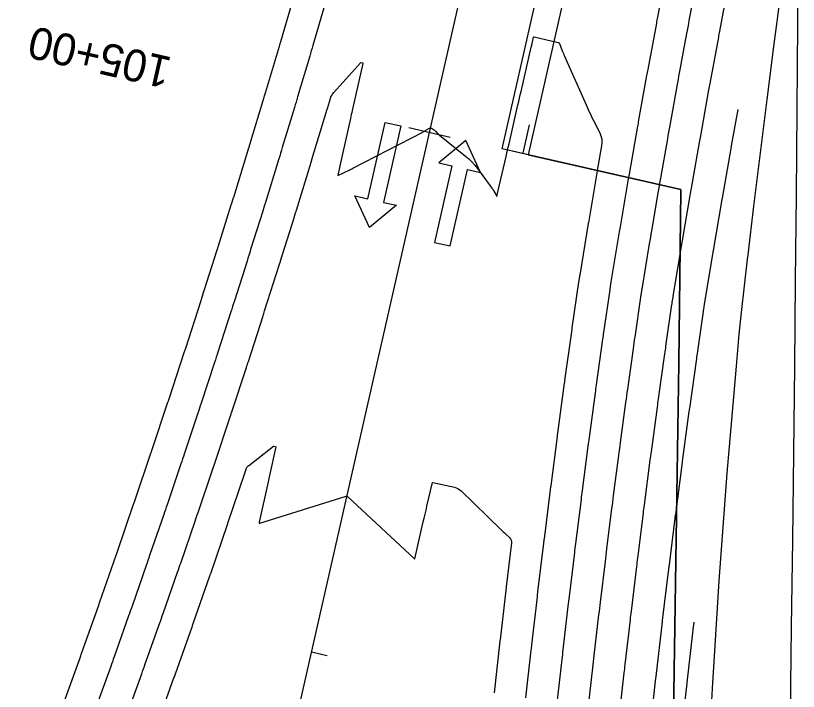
# Model space of a CAD drawing. Extents: x 1710723 to 1713003, y 548603 to 551142.
# Drawn here: x 1712345.3 to 1712492.2, y 550298.2 to 550424.9 of the extents above; entities that cross this region are included whole.
import ezdxf

# ---------------------------------------------------------------- set-up
doc = ezdxf.new("R2010")
doc.units = 0
for name, color, linetype in [('R_Contours', 7, 'Continuous'), ('R_Horz Alg', 7, 'Continuous'), ('R_Horz Alg Annot', 7, 'Continuous'), ('R_MOT', 7, 'Continuous'), ('R_No Plot', 7, 'Continuous'), ('R_Striping', 7, 'Continuous')]:
    doc.layers.add(name, color=color, linetype=linetype)

msp = doc.modelspace()

# ---------------------------------------------------------------- linework, layer by layer
at = {"layer": 'R_Contours'}
for points in [[(1712467.36, 550433.38), (1712465.71, 550424.66), (1712465.65, 550424.38), (1712465.6, 550424.1), (1712465.55, 550423.81), (1712465.5, 550423.53), (1712463.89, 550414.84), (1712463.83, 550414.55), (1712463.78, 550414.26), (1712463.73, 550413.96), (1712463.67, 550413.67), (1712462.11, 550405.01), (1712462.06, 550404.71), (1712462, 550404.4), (1712461.95, 550404.1), (1712461.89, 550403.8), (1712460.38, 550395.17), (1712460.32, 550394.86), (1712460.27, 550394.54), (1712460.22, 550394.23), (1712460.16, 550393.92), (1712458.69, 550385.32), (1712458.64, 550385), (1712458.58, 550384.67), (1712458.53, 550384.35), (1712458.48, 550384.02), (1712456.98, 550375.01), (1712456.96, 550374.9), (1712456.94, 550374.79), (1712456.92, 550374.68), (1712456.91, 550374.57), (1712456.76, 550373.68), (1712456.76, 550373.64), (1712456.75, 550373.6), (1712456.74, 550373.56), (1712456.74, 550373.52), (1712455.58, 550365.49), (1712455.54, 550365.18), (1712455.49, 550364.86), (1712455.45, 550364.55), (1712455.4, 550364.24), (1712454.21, 550355.67), (1712454.16, 550355.3), (1712454.11, 550354.92), (1712454.06, 550354.55), (1712454, 550354.18), (1712452.87, 550345.76), (1712452.82, 550345.37), (1712452.77, 550344.97), (1712452.71, 550344.58), (1712452.66, 550344.19), (1712451.58, 550335.83), (1712451.52, 550335.42), (1712451.47, 550335.01), (1712451.42, 550334.6), (1712451.37, 550334.19), (1712450.33, 550325.9), (1712450.27, 550325.47), (1712450.22, 550325.04), (1712450.17, 550324.62), (1712450.12, 550324.19), (1712449.12, 550315.95), (1712449.07, 550315.51), (1712449.02, 550315.06), (1712448.96, 550314.62), (1712448.91, 550314.17), (1712447.96, 550305.99), (1712447.91, 550305.53), (1712447.86, 550305.07), (1712447.81, 550304.61), (1712447.75, 550304.15), (1712446.85, 550296.02)], [(1712452.72, 550294.9), (1712453.58, 550302.57), (1712453.64, 550303.15), (1712453.71, 550303.74), (1712453.78, 550304.33), (1712453.85, 550304.92), (1712454.73, 550312.55), (1712454.8, 550313.14), (1712454.87, 550313.73), (1712454.94, 550314.33), (1712455.01, 550314.92), (1712455.93, 550322.52), (1712456, 550323.12), (1712456.07, 550323.71), (1712456.15, 550324.31), (1712456.22, 550324.91), (1712457.17, 550332.48), (1712457.25, 550333.08), (1712457.32, 550333.69), (1712457.4, 550334.29), (1712457.48, 550334.89), (1712458.46, 550342.43), (1712458.54, 550343.04), (1712458.62, 550343.65), (1712458.7, 550344.25), (1712458.78, 550344.86), (1712459.79, 550352.36), (1712459.87, 550352.98), (1712459.96, 550353.6), (1712460.04, 550354.21), (1712460.13, 550354.83), (1712461.19, 550362.45), (1712461.27, 550362.99), (1712461.34, 550363.54), (1712461.42, 550364.08), (1712461.5, 550364.62), (1712462.58, 550372.13), (1712462.59, 550372.2), (1712462.6, 550372.27), (1712462.61, 550372.35), (1712462.62, 550372.42), (1712462.77, 550373.31), (1712462.78, 550373.38), (1712462.79, 550373.46), (1712462.81, 550373.54), (1712462.82, 550373.61), (1712464.23, 550382.12), (1712464.33, 550382.73), (1712464.44, 550383.34), (1712464.54, 550383.95), (1712464.64, 550384.56), (1712465.91, 550391.99), (1712466.02, 550392.6), (1712466.12, 550393.21), (1712466.23, 550393.83), (1712466.34, 550394.44), (1712467.64, 550401.84), (1712467.74, 550402.46), (1712467.85, 550403.08), (1712467.96, 550403.69), (1712468.07, 550404.31), (1712469.41, 550411.7), (1712469.52, 550412.31), (1712469.63, 550412.93), (1712469.74, 550413.54), (1712469.86, 550414.16), (1712471.23, 550421.54), (1712471.34, 550422.16), (1712471.45, 550422.77), (1712471.57, 550423.38), (1712471.68, 550423.99), (1712473.09, 550431.38)], [(1712458.54, 550293.21), (1712459.47, 550301.62), (1712459.52, 550302.01), (1712459.56, 550302.41), (1712459.61, 550302.81), (1712459.65, 550303.21), (1712460.63, 550311.61), (1712460.67, 550312.01), (1712460.72, 550312.4), (1712460.77, 550312.8), (1712460.81, 550313.2), (1712461.83, 550321.6), (1712461.88, 550321.99), (1712461.92, 550322.39), (1712461.97, 550322.78), (1712462.02, 550323.17), (1712463.08, 550331.58), (1712463.12, 550331.97), (1712463.17, 550332.36), (1712463.22, 550332.74), (1712463.27, 550333.13), (1712464.37, 550341.55), (1712464.42, 550341.93), (1712464.47, 550342.32), (1712464.52, 550342.7), (1712464.57, 550343.08), (1712465.71, 550351.51), (1712465.76, 550351.89), (1712465.81, 550352.27), (1712465.86, 550352.65), (1712465.91, 550353.03), (1712467.09, 550361.46), (1712467.14, 550361.83), (1712467.2, 550362.21), (1712467.25, 550362.58), (1712467.3, 550362.95), (1712468.42, 550370.74), (1712468.44, 550370.84), (1712468.45, 550370.95), (1712468.47, 550371.05), (1712468.49, 550371.15), (1712468.63, 550372.04), (1712468.64, 550372.09), (1712468.65, 550372.13), (1712468.65, 550372.18), (1712468.66, 550372.22), (1712470.17, 550381.31), (1712470.23, 550381.66), (1712470.29, 550382.01), (1712470.35, 550382.37), (1712470.41, 550382.72), (1712471.86, 550391.21), (1712471.92, 550391.55), (1712471.97, 550391.89), (1712472.03, 550392.22), (1712472.09, 550392.56), (1712473.59, 550401.1), (1712473.65, 550401.43), (1712473.71, 550401.75), (1712473.76, 550402.07), (1712473.82, 550402.39), (1712475.37, 550410.99), (1712475.43, 550411.3), (1712475.48, 550411.6), (1712475.54, 550411.9), (1712475.59, 550412.2), (1712477.2, 550420.87), (1712477.25, 550421.15), (1712477.3, 550421.44), (1712477.36, 550421.72), (1712477.41, 550422.01), (1712479.07, 550430.74)], [(1712354.31, 550296.02), (1712357.41, 550304.65), (1712357.48, 550304.86), (1712357.56, 550305.07), (1712357.63, 550305.27), (1712357.7, 550305.48), (1712360.78, 550314.18), (1712360.85, 550314.37), (1712360.92, 550314.56), (1712360.99, 550314.75), (1712361.05, 550314.94), (1712364.11, 550323.71), (1712364.17, 550323.89), (1712364.23, 550324.06), (1712364.29, 550324.23), (1712364.35, 550324.41), (1712367.4, 550333.26), (1712367.45, 550333.42), (1712367.5, 550333.57), (1712367.56, 550333.73), (1712367.61, 550333.88), (1712370.64, 550342.83), (1712370.69, 550342.96), (1712370.73, 550343.09), (1712370.77, 550343.22), (1712370.82, 550343.35), (1712373.84, 550352.42), (1712373.87, 550352.52), (1712373.91, 550352.63), (1712373.94, 550352.73), (1712373.98, 550352.84), (1712376.97, 550361.95), (1712377.01, 550362.06), (1712377.04, 550362.17), (1712377.08, 550362.28), (1712377.11, 550362.39), (1712380.05, 550371.49), (1712380.09, 550371.6), (1712380.13, 550371.72), (1712380.17, 550371.84), (1712380.21, 550371.96), (1712383.09, 550381.02), (1712383.13, 550381.15), (1712383.17, 550381.29), (1712383.21, 550381.42), (1712383.26, 550381.55), (1712385.73, 550389.46), (1712385.77, 550389.59), (1712385.81, 550389.71), (1712385.85, 550389.84), (1712385.89, 550389.96), (1712386.16, 550390.82), (1712386.18, 550390.88), (1712386.18, 550390.9), (1712389.02, 550400.11), (1712389.07, 550400.28), (1712389.12, 550400.44), (1712389.17, 550400.61), (1712389.22, 550400.78), (1712391.91, 550409.66), (1712391.97, 550409.85), (1712392.03, 550410.04), (1712392.08, 550410.23), (1712392.14, 550410.42), (1712394.76, 550419.22), (1712394.83, 550419.43), (1712394.89, 550419.64), (1712394.95, 550419.86), (1712395.02, 550420.07), (1712397.59, 550428.88)], [(1712403.28, 550426.98), (1712401.03, 550419.29), (1712400.88, 550418.8), (1712400.74, 550418.32), (1712400.6, 550417.83), (1712400.45, 550417.35), (1712398.18, 550409.71), (1712398.03, 550409.21), (1712397.88, 550408.71), (1712397.73, 550408.21), (1712397.58, 550407.71), (1712395.3, 550400.2), (1712395.14, 550399.66), (1712394.97, 550399.12), (1712394.81, 550398.58), (1712394.64, 550398.04), (1712392.07, 550389.68), (1712392.04, 550389.6), (1712392.02, 550389.53), (1712392, 550389.46), (1712391.98, 550389.39), (1712391.71, 550388.52), (1712391.69, 550388.45), (1712391.66, 550388.38), (1712391.64, 550388.31), (1712391.62, 550388.24), (1712389.36, 550381.04), (1712389.19, 550380.5), (1712389.02, 550379.96), (1712388.85, 550379.42), (1712388.68, 550378.88), (1712386.31, 550371.43), (1712386.15, 550370.91), (1712385.98, 550370.39), (1712385.81, 550369.88), (1712385.65, 550369.36), (1712383.21, 550361.82), (1712383.05, 550361.33), (1712382.89, 550360.84), (1712382.73, 550360.35), (1712382.57, 550359.86), (1712380.07, 550352.23), (1712379.91, 550351.76), (1712379.76, 550351.3), (1712379.61, 550350.83), (1712379.45, 550350.37), (1712376.89, 550342.69), (1712376.74, 550342.23), (1712376.58, 550341.77), (1712376.42, 550341.3), (1712376.27, 550340.84), (1712373.67, 550333.17), (1712373.51, 550332.7), (1712373.36, 550332.24), (1712373.2, 550331.78), (1712373.04, 550331.32), (1712370.4, 550323.65), (1712370.24, 550323.19), (1712370.09, 550322.73), (1712369.93, 550322.27), (1712369.77, 550321.81), (1712367.09, 550314.14), (1712366.93, 550313.68), (1712366.77, 550313.23), (1712366.61, 550312.77), (1712366.45, 550312.32), (1712363.73, 550304.64), (1712363.57, 550304.19), (1712363.41, 550303.74), (1712363.25, 550303.28), (1712363.09, 550302.83), (1712360.33, 550295.16)], [(1712366.2, 550293.9), (1712368.93, 550301.48), (1712369.09, 550301.94), (1712369.26, 550302.41), (1712369.43, 550302.87), (1712369.59, 550303.34), (1712372.31, 550311.01), (1712372.47, 550311.46), (1712372.62, 550311.9), (1712372.78, 550312.34), (1712372.93, 550312.79), (1712375.64, 550320.56), (1712375.79, 550320.98), (1712375.94, 550321.4), (1712376.08, 550321.82), (1712376.23, 550322.24), (1712378.94, 550330.12), (1712379.07, 550330.52), (1712379.21, 550330.91), (1712379.34, 550331.31), (1712379.48, 550331.71), (1712382.18, 550339.7), (1712382.31, 550340.07), (1712382.43, 550340.44), (1712382.56, 550340.8), (1712382.68, 550341.17), (1712385.4, 550349.32), (1712385.5, 550349.64), (1712385.61, 550349.97), (1712385.72, 550350.29), (1712385.83, 550350.62), (1712388.56, 550358.95), (1712388.65, 550359.23), (1712388.74, 550359.51), (1712388.84, 550359.79), (1712388.93, 550360.07), (1712391.69, 550368.61), (1712391.76, 550368.84), (1712391.83, 550369.07), (1712391.91, 550369.29), (1712391.98, 550369.52), (1712394.78, 550378.32), (1712394.83, 550378.47), (1712394.88, 550378.63), (1712394.93, 550378.79), (1712394.97, 550378.94), (1712397.51, 550387.02), (1712397.53, 550387.08), (1712397.8, 550387.95), (1712397.84, 550388.08), (1712397.87, 550388.2), (1712397.91, 550388.33), (1712397.95, 550388.45), (1712400.78, 550397.65), (1712400.8, 550397.72), (1712400.83, 550397.79), (1712400.85, 550397.86), (1712400.87, 550397.93), (1712403.72, 550407.35), (1712403.74, 550407.4), (1712403.78, 550407.53), (1712404.32, 550409.37), (1712404.43, 550409.67), (1712404.57, 550409.96), (1712404.74, 550410.22), (1712404.94, 550410.48), (1712410.01, 550416.16), (1712410.02, 550416.16), (1712410.32, 550416.1), (1712410.36, 550416.08), (1712410.39, 550416.05), (1712410.4, 550416.02), (1712410.4, 550415.97), (1712408.42, 550407.1), (1712408.33, 550406.73), (1712408.25, 550406.36), (1712408.17, 550405.98), (1712408.08, 550405.61), (1712406.11, 550396.74), (1712406.07, 550396.6), (1712406.04, 550396.45), (1712405.71, 550394.96), (1712405.71, 550394.94), (1712405.71, 550394.93), (1712405.73, 550394.93), (1712405.75, 550394.93), (1712407.86, 550395.95), (1712408.03, 550396.03), (1712408.2, 550396.11), (1712408.37, 550396.2), (1712408.53, 550396.28), (1712421.65, 550403.09), (1712421.8, 550403.17), (1712421.95, 550403.25), (1712422.09, 550403.33), (1712422.24, 550403.41), (1712422.93, 550403.8), (1712423.02, 550403.84), (1712423.12, 550403.85), (1712423.22, 550403.83), (1712423.32, 550403.79), (1712423.7, 550403.55), (1712423.8, 550403.49), (1712423.89, 550403.42), (1712423.97, 550403.34), (1712424.05, 550403.26), (1712424.44, 550402.84), (1712424.53, 550402.74), (1712424.63, 550402.65), (1712424.73, 550402.56), (1712424.83, 550402.47), (1712429.66, 550398.59), (1712430.28, 550398.06), (1712430.87, 550397.49), (1712431.41, 550396.88), (1712431.92, 550396.24), (1712434.65, 550392.56), (1712434.74, 550392.42), (1712434.83, 550392.29), (1712434.92, 550392.15), (1712435, 550392.01), (1712435.55, 550391.03), (1712435.56, 550391.02), (1712435.57, 550391.01), (1712435.58, 550391.02), (1712435.58, 550391.04), (1712437.31, 550398.52), (1712437.44, 550399.11), (1712437.58, 550399.7), (1712437.71, 550400.28), (1712437.85, 550400.87), (1712439.53, 550408.18), (1712439.67, 550408.81), (1712439.82, 550409.44), (1712439.96, 550410.07), (1712440.11, 550410.71), (1712442.02, 550419.02), (1712442.06, 550419.19), (1712442.1, 550419.36), (1712442.44, 550420.87), (1712442.46, 550420.91), (1712442.48, 550420.93), (1712442.51, 550420.94), (1712442.55, 550420.94), (1712447.06, 550419.91), (1712447.15, 550419.88), (1712447.23, 550419.83), (1712447.29, 550419.76), (1712447.33, 550419.68), (1712447.84, 550418.34), (1712447.94, 550418.08), (1712448.05, 550417.83), (1712448.15, 550417.58), (1712448.26, 550417.33), (1712452.58, 550407.61), (1712452.85, 550407.02), (1712453.13, 550406.43), (1712453.41, 550405.84), (1712453.7, 550405.26), (1712454.87, 550402.94), (1712455.11, 550402.35), (1712455.25, 550401.74), (1712455.29, 550401.13), (1712455.23, 550400.49), (1712454.42, 550395.9), (1712454.42, 550395.86), (1712454.41, 550395.84), (1712452.75, 550386.08), (1712452.74, 550386.04), (1712452.73, 550386), (1712452.73, 550385.96), (1712452.72, 550385.92), (1712451.11, 550376.25), (1712451.1, 550376.18), (1712451.09, 550376.12), (1712451.08, 550376.05), (1712451.07, 550375.99), (1712450.9, 550374.95), (1712450.9, 550374.92), (1712450.89, 550374.92), (1712449.66, 550366.36), (1712449.65, 550366.28), (1712449.64, 550366.19), (1712449.63, 550366.11), (1712449.62, 550366.02), (1712448.29, 550356.51), (1712448.27, 550356.38), (1712448.25, 550356.25), (1712448.24, 550356.13), (1712448.22, 550356), (1712446.96, 550346.61), (1712446.93, 550346.46), (1712446.91, 550346.3), (1712446.89, 550346.15), (1712446.87, 550345.99), (1712445.67, 550336.71), (1712445.64, 550336.53), (1712445.62, 550336.34), (1712445.6, 550336.16), (1712445.57, 550335.97), (1712444.42, 550326.79), (1712444.4, 550326.58), (1712444.37, 550326.37), (1712444.34, 550326.16), (1712444.32, 550325.95), (1712443.22, 550316.87), (1712443.19, 550316.63), (1712443.16, 550316.39), (1712443.14, 550316.15), (1712443.11, 550315.92), (1712442.07, 550306.92), (1712442.04, 550306.66), (1712442.01, 550306.4), (1712441.98, 550306.14), (1712441.95, 550305.87), (1712440.96, 550296.97)], [(1712480.8, 550407.31), (1712479.56, 550400.47), (1712479.56, 550400.42), (1712479.55, 550400.37), (1712477.84, 550390.66), (1712477.83, 550390.61), (1712477.82, 550390.56), (1712477.82, 550390.5), (1712477.81, 550390.45), (1712476.17, 550380.85), (1712476.15, 550380.77), (1712476.14, 550380.69), (1712476.12, 550380.61), (1712476.11, 550380.52), (1712474.5, 550370.83), (1712474.49, 550370.78), (1712474.33, 550369.8), (1712474.32, 550369.71), (1712474.3, 550369.62), (1712474.29, 550369.52), (1712474.28, 550369.43), (1712473.08, 550361.13), (1712473.06, 550361), (1712473.05, 550360.88), (1712473.03, 550360.75), (1712473.01, 550360.63), (1712471.7, 550351.23), (1712471.68, 550351.08), (1712471.66, 550350.94), (1712471.64, 550350.79), (1712471.62, 550350.65), (1712470.36, 550341.3), (1712470.34, 550341.15), (1712470.32, 550340.99), (1712470.3, 550340.83), (1712470.28, 550340.67), (1712469.07, 550331.37), (1712469.05, 550331.2), (1712469.03, 550331.03), (1712469, 550330.85), (1712468.98, 550330.68), (1712467.82, 550321.43), (1712467.8, 550321.24), (1712467.78, 550321.06), (1712467.75, 550320.87), (1712467.73, 550320.68), (1712466.62, 550311.48), (1712466.6, 550311.28), (1712466.57, 550311.08), (1712466.55, 550310.88), (1712466.52, 550310.68), (1712465.46, 550301.51), (1712465.44, 550301.3), (1712465.41, 550301.08), (1712465.39, 550300.87), (1712465.37, 550300.66), (1712464.35, 550291.52)], [(1712371.88, 550292.07), (1712374.97, 550300.68), (1712375.04, 550300.88), (1712375.11, 550301.08), (1712375.18, 550301.28), (1712375.26, 550301.48), (1712378.36, 550310.25), (1712378.42, 550310.41), (1712378.47, 550310.57), (1712378.53, 550310.73), (1712378.59, 550310.89), (1712381.71, 550319.84), (1712381.75, 550319.96), (1712381.79, 550320.07), (1712381.83, 550320.19), (1712381.87, 550320.3), (1712385.02, 550329.46), (1712385.04, 550329.52), (1712385.06, 550329.58), (1712385.08, 550329.65), (1712385.1, 550329.71), (1712388.28, 550339.09), (1712388.29, 550339.12), (1712388.59, 550340.03), (1712388.65, 550340.17), (1712388.72, 550340.29), (1712388.82, 550340.4), (1712388.93, 550340.5), (1712393.63, 550344.14), (1712393.65, 550344.15), (1712393.67, 550344.16), (1712393.68, 550344.16), (1712393.7, 550344.16), (1712394.01, 550344.09), (1712394.03, 550344.08), (1712394.05, 550344.06), (1712394.06, 550344.04), (1712394.06, 550344.01), (1712392.88, 550338.69), (1712392.81, 550338.39), (1712392.75, 550338.09), (1712392.68, 550337.8), (1712392.62, 550337.5), (1712390.93, 550329.89), (1712390.93, 550329.8), (1712390.95, 550329.74), (1712391.01, 550329.72), (1712391.11, 550329.73), (1712407.31, 550334.77), (1712407.33, 550334.78), (1712407.36, 550334.79), (1712407.42, 550334.81), (1712407.43, 550334.81), (1712407.43, 550334.81), (1712407.44, 550334.81), (1712407.44, 550334.81), (1712407.5, 550334.75), (1712407.52, 550334.74), (1712407.53, 550334.73), (1712420.11, 550323.05), (1712420.12, 550323.04), (1712420.13, 550323.04), (1712420.14, 550323.04), (1712420.15, 550323.06), (1712421.75, 550329.94), (1712421.93, 550330.68), (1712422.1, 550331.43), (1712422.27, 550332.17), (1712422.45, 550332.92), (1712423.48, 550337.35), (1712423.48, 550337.37), (1712423.5, 550337.38), (1712423.51, 550337.38), (1712423.53, 550337.38), (1712427.61, 550336.46), (1712427.94, 550336.36), (1712428.24, 550336.22), (1712428.52, 550336.04), (1712428.78, 550335.82), (1712436.37, 550328.48), (1712436.57, 550328.29), (1712436.77, 550328.1), (1712436.97, 550327.91), (1712437.17, 550327.72), (1712437.98, 550326.97), (1712438.15, 550326.78), (1712438.27, 550326.56), (1712438.32, 550326.31), (1712438.32, 550326.05), (1712437.32, 550317.78), (1712437.32, 550317.75), (1712437.31, 550317.72), (1712437.31, 550317.69), (1712437.31, 550317.66), (1712436.17, 550307.86), (1712436.16, 550307.79), (1712436.15, 550307.73), (1712436.15, 550307.66), (1712436.14, 550307.6), (1712435.06, 550297.92)], [(1712470.16, 550289.84), (1712471.26, 550299.71), (1712471.26, 550299.76), (1712471.27, 550299.8), (1712472.42, 550309.74), (1712472.42, 550309.75), (1712472.59, 550311.12)]]:
    msp.add_lwpolyline(points, dxfattribs=at)
at = {"layer": 'R_Horz Alg'}
msp.add_line((1712246.77, 549627.28), (1712450.81, 550525.82), dxfattribs=at)
at = {"layer": 'R_Horz Alg Annot'}
for points in [[(1712419.02, 550403.91), (1712426.82, 550402.14)], [(1712403.7, 550304.84), (1712400.78, 550305.5)]]:
    msp.add_lwpolyline(points, dxfattribs=at)
at = {"layer": 'R_MOT'}
for p, q in [((1712436.58, 550399.92), (1712464.46, 550522.72)), ((1712440.51, 550399.15), (1712441.72, 550404.47)), ((1712444.37, 550398.15), (1712436.57, 550399.93))]:
    msp.add_line(p, q, dxfattribs=at)
for points in [[(1712492.15, 550449.84), (1712491.56, 550448.96), (1712490.17, 550439.03), (1712488.83, 550429.07), (1712487.51, 550419.12), (1712486.22, 550409.16), (1712484.96, 550399.19), (1712483.75, 550389.21), (1712482.67, 550380.07), (1712482.57, 550379.22), (1712481.44, 550369.23), (1712481, 550365.15), (1712480.5, 550359.18), (1712479.61, 550349.13), (1712478.76, 550339.07), (1712477.98, 550328.99), (1712477.25, 550318.9), (1712476.59, 550308.8), (1712475.95, 550298.69), (1712475.41, 550288.56)], [(1712490.68, 550293.9), (1712490.89, 550310.22), (1712491.1, 550326.54), (1712491.3, 550342.86), (1712491.51, 550359.17), (1712491.64, 550375.22), (1712491.78, 550391.26), (1712491.91, 550407.31), (1712492.04, 550423.35), (1712492.11, 550439.15), (1712492.15, 550449.84)], [(1712488.83, 550429.07), (1712487.51, 550419.12), (1712486.22, 550409.16), (1712484.96, 550399.19), (1712483.75, 550389.21), (1712482.67, 550380.07), (1712482.57, 550379.22), (1712481.44, 550369.23), (1712481, 550365.15), (1712480.5, 550359.18), (1712479.61, 550349.13), (1712478.76, 550339.07), (1712477.98, 550328.99), (1712477.25, 550318.9), (1712476.59, 550308.8), (1712475.95, 550298.69), (1712475.41, 550288.56)], [(1712470.12, 550392.31), (1712436.58, 550399.92)], [(1712467.79, 550127.25), (1712467.73, 550141.12), (1712467.61, 550165.79), (1712467.86, 550181.67), (1712468.11, 550197.55), (1712468.36, 550213.43), (1712468.61, 550229.32), (1712468.64, 550245.44), (1712468.67, 550261.56), (1712468.7, 550277.69), (1712468.73, 550293.81), (1712468.98, 550310.3), (1712469.24, 550326.8), (1712469.49, 550343.3), (1712469.75, 550359.79), (1712469.93, 550375.99), (1712470.11, 550392.19), (1712470.12, 550392.31)]]:
    msp.add_lwpolyline(points, dxfattribs=at)
for points in [[(1712416.74, 550389.34), (1712411.69, 550385.16), (1712408.94, 550391.11), (1712411.38, 550390.56), (1712414.63, 550404.9), (1712417.56, 550404.24), (1712414.3, 550389.89)], [(1712432.5, 550395.52), (1712429.75, 550401.47), (1712424.7, 550397.29), (1712427.14, 550396.74), (1712423.88, 550382.39), (1712426.8, 550381.73), (1712430.06, 550396.08)]]:
    msp.add_lwpolyline(points, close=True, dxfattribs=at)
at = {"layer": 'R_No Plot'}
for p, q in [((1712463.59, 550496.33), (1712441.45, 550398.81)), ((1712441.45, 550398.81), (1712470.12, 550392.31))]:
    msp.add_line(p, q, dxfattribs=at)
msp.add_lwpolyline([(1712470.12, 550392.31), (1712470.11, 550392.19), (1712469.93, 550375.99), (1712469.75, 550359.79), (1712469.49, 550343.3), (1712469.24, 550326.8), (1712468.98, 550310.3), (1712468.73, 550293.81)], dxfattribs=at)
at = {"layer": 'R_Striping'}
msp.add_line((1712369.36, 550167.14), (1712450.81, 550525.82), dxfattribs=at)

# ---------------------------------------------------------------- texts
at = {"layer": 'R_Horz Alg Annot'}
msp.add_text('105+00', height=6, rotation=167.2066, dxfattribs=at).set_placement((1712374.83, 550417.02))

doc.saveas('drawing.dxf')
